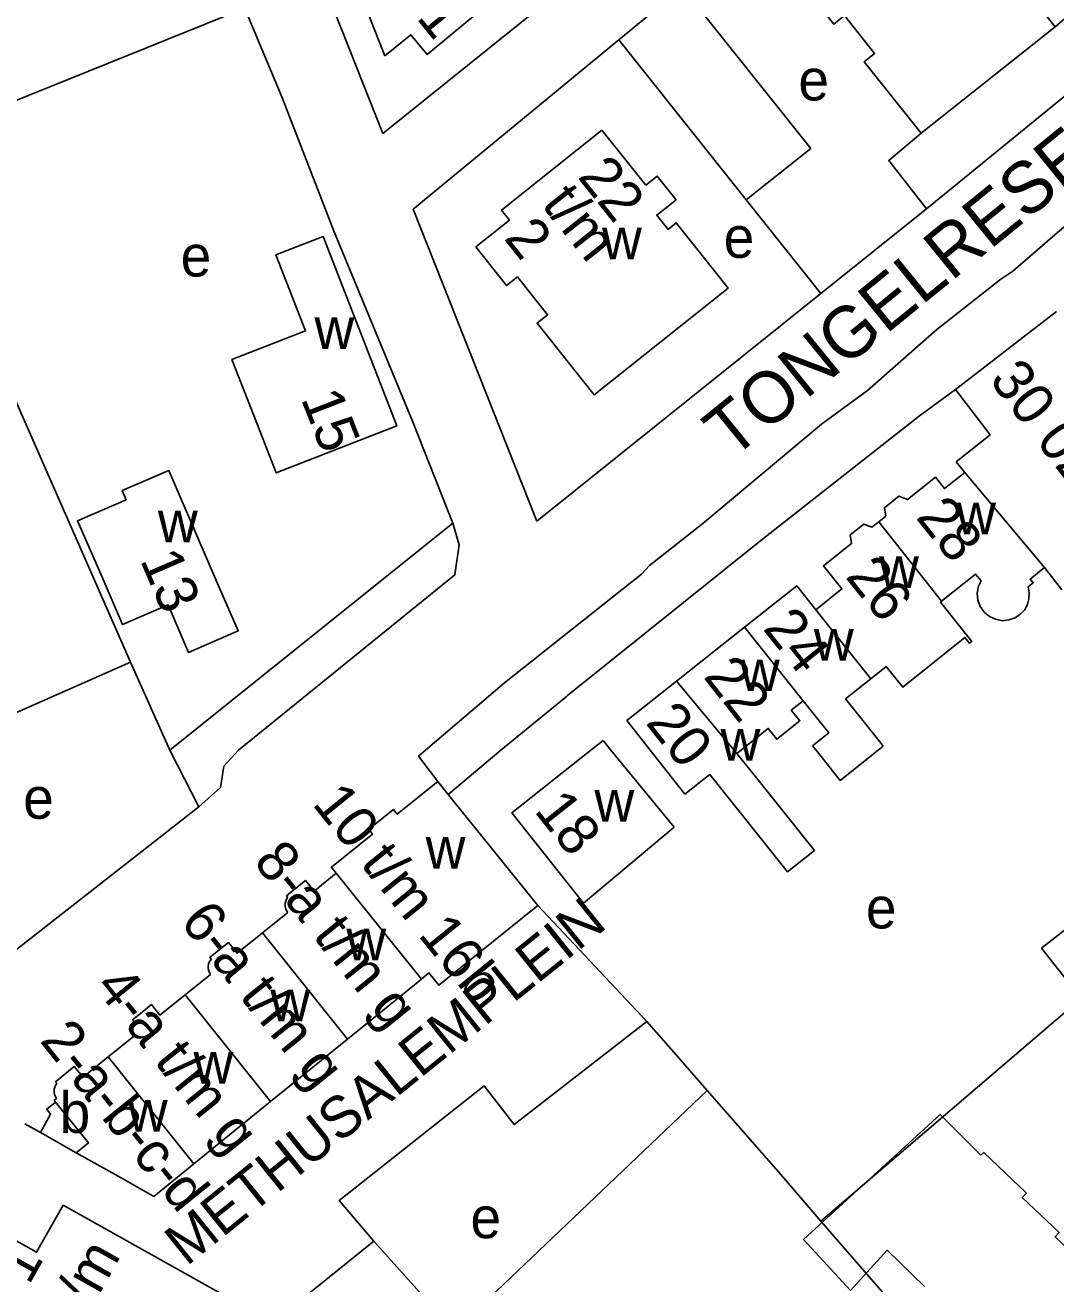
# Model space of a CAD drawing. Extents: x 161141 to 163125, y 381621 to 383200.
# Drawn here: x 161934.5 to 162034.5, y 382848.2 to 382970.4 of the extents above; entities that cross this region are included whole.
import ezdxf

# ---------------------------------------------------------------- set-up
doc = ezdxf.new("R2010")
doc.units = 0
for name, color, linetype in [('BLT_Basislijn', 7, 'Continuous'), ('BLT_Bebouwing', 7, 'Continuous'), ('BLT_Centroide', 7, 'Continuous'), ('BLT_Huisnummer', 7, 'Continuous'), ('BLT_Huisnummer_ tussenligend', 7, 'Continuous'), ('BLT_Huisnummer_reeks', 7, 'Continuous'), ('BLT_Onderverdeling_panden', 7, 'Continuous'), ('BLT_Plantopo', 7, 'Continuous'), ('BLT_Straatnaam', 7, 'Continuous'), ('BLT_Straatnaam_verkleind', 7, 'Continuous')]:
    doc.layers.add(name, color=color, linetype=linetype)

msp = doc.modelspace()

# ---------------------------------------------------------------- linework, layer by layer
at = {"layer": 'BLT_Basislijn'}
for p, q in [((161998.24, 382974.04), (161992.06, 382968.95)), ((162039.04, 382974.17), (162034.4, 382970.22)), ((161932.99, 382962.83), (161955.76, 382972.02)), ((161992.06, 382968.95), (161972.09, 382952.52)), ((161992.06, 382968.95), (162004.41, 382953.43)), ((162004.41, 382953.43), (162011.65, 382944.32)), ((162021.23, 382932.46), (162024.72, 382935.01)), ((162005.82, 382920.35), (162021.23, 382932.46)), ((161975.96, 382922.03), (161948.48, 382899.99)), ((162005.82, 382920.35), (161987.09, 382905.31)), ((161948.48, 382899.99), (161944.66, 382908.56)), ((161951.29, 382894.51), (161948.48, 382899.99)), ((161951.29, 382894.51), (161926.84, 382875.38)), ((161984.18, 382884.91), (161994.76, 382873.68)), ((162036.9, 382875.89), (162011.67, 382854.3)), ((161997.81, 382870.19), (161994.76, 382873.68)), ((162000.63, 382866.97), (161997.81, 382870.19)), ((161934.42, 382863.74), (161935.93, 382862.88)), ((162046.28, 382814.44), (162011.67, 382854.3)), ((161961.29, 382846.71), (161968.27, 382852.33))]:
    msp.add_line(p, q, dxfattribs=at)
for points in [[(161959.96, 382983.09), (161969.17, 382959.86), (162047.68, 383022.98)], [(162055.07, 383020.8), (162073.06, 382998.55), (162074.21, 382996.11), (162061.33, 382985.3), (162036.1, 382964.14), (162021.9, 382952.54)], [(161998.24, 382974.04), (162010.67, 382958.41), (162004.41, 382953.43)], [(161955.76, 382972.02), (161956.08, 382971.21), (161959.35, 382963.42), (161964.45, 382950.31), (161972.02, 382931.93), (161975.96, 382922.03)], [(162051.8, 382964.24), (162051.59, 382964.07), (162034.86, 382950.43), (162030.3, 382946.48), (162029.11, 382945.73), (162022.92, 382940.82), (162016.17, 382934.9), (162011.73, 382931.63), (162000.21, 382922), (161995.04, 382917.92), (161994.27, 382917.07), (161980.96, 382906.53), (161973.3, 382900), (161972.62, 382899.42), (161974.49, 382896.95)], [(162021.4, 382959.88), (162018.24, 382957.25), (162021.9, 382952.54)], [(161984.09, 382922.23), (161972.09, 382952.52)], [(162021.9, 382952.54), (162011.65, 382944.32)], [(162011.65, 382944.32), (161984.09, 382922.23)], [(161975.96, 382922.03), (161976.57, 382919.93), (161976.13, 382917.01), (161955.14, 382900), (161953.74, 382898.46), (161953.42, 382896.39), (161951.29, 382894.51)], [(161987.09, 382905.31), (161986.94, 382905.19), (161980.62, 382900), (161975.5, 382895.7)], [(162036.9, 382875.89), (162033.07, 382880.77), (162048.7, 382892.97)], [(161968.27, 382852.33), (161964.93, 382856.3), (161978.99, 382867.42), (161981.89, 382863.68), (161994.76, 382873.68)], [(162000.63, 382866.97), (161976.12, 382843.61), (161968.27, 382852.33)], [(162011.67, 382854.3), (162007.54, 382859.06), (162000.63, 382866.97)]]:
    msp.add_lwpolyline(points, dxfattribs=at)
at = {"layer": 'BLT_Bebouwing'}
for p, q in [((162024.72, 382935.01), (162034.52, 382942.57)), ((161930.52, 382940.74), (161944.66, 382908.56)), ((162025.62, 382926.97), (162024.8, 382927.98)), ((162033.36, 382917.72), (162035.04, 382915.55)), ((162023.37, 382914.47), (162023.26, 382914.38)), ((161989.35, 382900), (161990.54, 382900.94)), ((161990.54, 382900.94), (161991.29, 382900)), ((162010.86, 382900.41), (162011.19, 382900)), ((162017.71, 382900.38), (162017.23, 382900)), ((161975.5, 382895.7), (161974.49, 382896.95)), ((161957.47, 382882.28), (161959.93, 382884.26)), ((161949.98, 382876.26), (161952.44, 382878.24)), ((161965.72, 382871.96), (161972.9, 382877.79)), ((161942.51, 382870.24), (161944.95, 382872.2)), ((161958.26, 382865.9), (161965.72, 382871.96)), ((161950.82, 382859.85), (161958.26, 382865.9)), ((161939.4, 382860.92), (161935.93, 382862.88))]:
    msp.add_line(p, q, dxfattribs=at)
for points in [[(162021.4, 382959.88), (162015.87, 382966.83), (162016.87, 382967.63), (162013.95, 382971.31), (162012.91, 382970.48), (162009.92, 382974.24), (162013.19, 382976.83), (162012.41, 382977.82), (162022.16, 382985.58), (162026.42, 382980.23), (162027.52, 382981.11), (162029.35, 382978.82), (162027.47, 382977.32), (162028.57, 382975.93), (162029.35, 382976.56), (162034.4, 382970.22)], [(161977.96, 382971.24), (161973.46, 382967.52), (161971.87, 382969.44), (161969.36, 382967.41), (161966.93, 382973.59), (161972.39, 382978.09)], [(162034.4, 382970.22), (162021.4, 382959.88)], [(161958.79, 382948.07), (161963.36, 382949.85), (161970.52, 382931.48), (161958.81, 382926.92), (161956.99, 382931.58), (161954.52, 382937.91), (161961.66, 382940.69), (161958.79, 382948.07)], [(162024.8, 382927.98), (162028.1, 382930.61), (162024.72, 382935.01)], [(161953.13, 382916.17), (161948.38, 382927.14), (161943.88, 382925.2), (161944.26, 382924.31), (161939.54, 382922.27), (161941.92, 382916.78), (161943.91, 382912.19), (161948.32, 382914.1), (161950.31, 382909.49), (161955.12, 382911.59), (161953.13, 382916.17)], [(162025.62, 382926.97), (162023.65, 382925.4), (162022.77, 382926.49), (162020.06, 382924.32), (162019.22, 382924.65), (162017.83, 382923.54), (162017.96, 382922.72), (162017.28, 382922.18)], [(162017.28, 382922.18), (162016.61, 382921.64), (162015.83, 382921.94), (162014.5, 382920.89), (162014.63, 382920.07), (162011.9, 382917.9), (162013.7, 382915.66), (162011.17, 382913.64)], [(162033.36, 382917.72), (162031.98, 382916.61), (162032.27, 382916.25), (162031.77, 382915.85), (162031.88, 382915.28), (162031.84, 382914.7), (162031.71, 382914.18), (162031.44, 382913.63), (162031.01, 382913.2), (162030.51, 382912.86), (162029.91, 382912.64), (162029.27, 382912.57), (162028.59, 382912.71), (162028.03, 382912.99), (162027.54, 382913.38), (162027.11, 382913.94), (162026.9, 382914.55), (162026.84, 382915.24), (162026.96, 382915.91), (162027.21, 382916.43), (162026.67, 382917.1), (162023.37, 382914.47)], [(162011.17, 382913.64), (162009.32, 382915.95), (162004.24, 382911.93)], [(162023.26, 382914.38), (162026.31, 382910.56), (162026.09, 382910.38), (162025.64, 382910.94), (162019.6, 382906.12), (162018.01, 382908.12), (162016.52, 382906.93)], [(161997.65, 382906.71), (162000, 382908.57), (162004.24, 382911.93)], [(161944.66, 382908.56), (161925.31, 382900), (161922.35, 382898.69)], [(161992.82, 382902.88), (161997.65, 382906.71)], [(162016.52, 382906.93), (162014.06, 382904.97), (162017.28, 382900.93), (162017.71, 382900.38)], [(162009.94, 382904.8), (162008.79, 382903.88), (162009.62, 382902.85), (162007.38, 382901.07), (162006.55, 382902.11), (162003.52, 382899.69)], [(162010.86, 382900.41), (162012.43, 382901.67), (162009.94, 382904.8)], [(162003.52, 382899.69), (162005.55, 382897.14), (162011.04, 382890.27), (162008.43, 382888.19), (162000.89, 382897.64), (162000, 382896.95), (161998.47, 382895.74), (161995.1, 382900), (161992.82, 382902.88)], [(161989.35, 382900), (161981.68, 382893.93), (161988.63, 382885.16), (161997.42, 382892.53), (161991.29, 382900)], [(162017.23, 382900), (162013.54, 382897.05), (162011.19, 382900)], [(161964.64, 382888.06), (161964.17, 382888.65), (161968.15, 382891.86), (161967.8, 382892.34), (161970.18, 382894.25), (161970.56, 382893.78), (161974.49, 382896.95)], [(161984.18, 382884.91), (161975.5, 382895.7)], [(161960.72, 382886.61), (161961.64, 382887.36), (161962.48, 382886.32), (161964.64, 382888.06)], [(161959.92, 382885.72), (161959.8, 382885.85), (161960.72, 382886.61)], [(161959.92, 382885.72), (161959.77, 382885.45), (161959.68, 382885.16), (161959.68, 382884.85), (161959.75, 382884.56), (161959.9, 382884.29), (161959.93, 382884.26)], [(161972.9, 382877.79), (161973.63, 382878.38), (161974.59, 382877.19), (161984.18, 382884.91)], [(161953.28, 382880.61), (161954.18, 382881.33), (161955.01, 382880.3), (161957.47, 382882.28)], [(161952.36, 382879.54), (161952.54, 382879.69), (161952.38, 382879.88), (161953.28, 382880.61)], [(161952.36, 382879.54), (161952.25, 382879.25), (161952.21, 382878.94), (161952.25, 382878.64), (161952.37, 382878.35), (161952.44, 382878.24)], [(161945.79, 382874.58), (161946.7, 382875.32), (161947.52, 382874.27), (161949.98, 382876.26)], [(161945, 382873.69), (161944.88, 382873.84), (161945.79, 382874.58)], [(161945, 382873.69), (161944.83, 382873.42), (161944.74, 382873.12), (161944.73, 382872.81), (161944.8, 382872.5), (161944.94, 382872.22), (161944.95, 382872.2)], [(161937.53, 382867.67), (161937.4, 382867.8), (161939.21, 382869.3), (161940.08, 382868.27), (161942.51, 382870.24)], [(161937.53, 382867.67), (161937.37, 382867.4), (161937.28, 382867.1), (161937.27, 382866.78), (161937.34, 382866.47), (161937.48, 382866.19), (161937.49, 382866.18)], [(161935.93, 382862.88), (161936.92, 382864.67), (161936.54, 382865.17), (161937.39, 382865.84)], [(161937.39, 382865.84), (161937.27, 382866.01), (161937.49, 382866.18)], [(161950.82, 382859.85), (161946.94, 382856.69), (161943.76, 382858.48), (161939.4, 382860.92)], [(161921.65, 382853.48), (161925.76, 382856.78), (161935.56, 382851.27), (161938.14, 382855.85)], [(161938.14, 382855.85), (161955.63, 382846.03)]]:
    msp.add_lwpolyline(points, dxfattribs=at)
msp.add_lwpolyline([(161990.42, 382960.19), (161994.68, 382954.85), (161995.78, 382955.73), (161997.61, 382953.43), (161995.73, 382951.94), (161996.83, 382950.55), (161997.62, 382951.18), (162002.66, 382944.84), (161989.66, 382934.5), (161984.13, 382941.45), (161985.13, 382942.25), (161982.21, 382945.93), (161981.17, 382945.1), (161978.18, 382948.85), (161981.45, 382951.45), (161980.67, 382952.43)], close=True, dxfattribs=at)
at = {"layer": 'BLT_Onderverdeling_panden'}
for p, q in [((162033.36, 382917.72), (162025.62, 382926.97)), ((162017.28, 382922.18), (162023.37, 382914.47)), ((162011.17, 382913.64), (162016.52, 382906.93)), ((162004.24, 382911.93), (162009.94, 382904.8)), ((161997.65, 382906.71), (162003.52, 382899.69)), ((161964.64, 382888.06), (161972.9, 382877.79)), ((161957.47, 382882.28), (161965.72, 382871.96)), ((161949.98, 382876.26), (161958.26, 382865.9)), ((161942.51, 382870.24), (161950.82, 382859.85))]:
    msp.add_line(p, q, dxfattribs=at)
msp.add_lwpolyline([(161939.4, 382860.92), (161940.59, 382861.88), (161937.39, 382865.84)], dxfattribs=at)
at = {"layer": 'BLT_Plantopo'}
msp.add_lwpolyline([(162021.72, 382847.94), (162018.1, 382851.46), (162014.52, 382847.57), (162009.98, 382852.51), (162023.22, 382864.65), (162027.18, 382860.7), (162027.47, 382860.94), (162031.61, 382857.01), (162031.2, 382856.58), (162034.77, 382853.19), (162034.39, 382852.78), (162038.08, 382849.28), (162037.69, 382848.87), (162041.31, 382845.43)], dxfattribs=at)

# ---------------------------------------------------------------- texts
at = {"layer": 'BLT_Centroide'}
for s, p in [('e', (162009.48, 382963.07)), ('w', (161990.42, 382947.64)), ('e', (162002.23, 382947.79)), ('e', (161949.54, 382945.98)), ('w', (161962.52, 382938.95)), ('w', (161947.33, 382920.17)), ('w', (162024.78, 382920.94)), ('w', (162017.3, 382915.73)), ('w', (162010.98, 382908.69)), ('w', (162003.8, 382905.73)), ('w', (162001.92, 382898.97)), ('e', (161934.26, 382893.35)), ('w', (161989.69, 382893.06)), ('w', (161973.31, 382888.5)), ('e', (162016.03, 382882.7)), ('w', (161965.62, 382879.61)), ('w', (161958.25, 382873.67)), ('w', (161950.78, 382867.64)), ('b', (161937.79, 382862.85)), ('w', (161944.41, 382862.98)), ('e', (161977.66, 382852.64))]:
    msp.add_text(s, height=4, dxfattribs=at).set_placement(p)
at = {"layer": 'BLT_Huisnummer'}
for s, rotation, p in [('1', 309.2052, (161972.34, 382971.07)), ('15', 291.2843, (161961.18, 382934.14)), ('13', 293.4122, (161945.56, 382918.47)), ('26', 308.5922, (162013.96, 382916.83)), ('24', 308.5922, (162005.95, 382911.79)), ('20', 308.3616, (161994.58, 382902.65)), ('18', 308.3777, (161983.76, 382894.12))]:
    msp.add_text(s, height=4, rotation=rotation, dxfattribs=at).set_placement(p)
at = {"layer": 'BLT_Huisnummer_ tussenligend'}
for s, rotation, p in [('28', 308.5942, (162020.79, 382922.59)), ('22', 308.3616, (162000.18, 382907.12))]:
    msp.add_text(s, height=4, rotation=rotation, dxfattribs=at).set_placement(p)
at = {"layer": 'BLT_Huisnummer_reeks'}
for s, rotation, p in [('22', 308.5068, (161987.98, 382955.64)), ('t/m', 308.5074, (161984.48, 382952.94)), ('2', 308.5067, (161980.83, 382949.68)), ('30 02 t/m 30 40', 307.5492, (162027.91, 382935.93)), ('10 t/m 16b', 308.9445, (161962.22, 382894.77)), ('8-a t/m g', 308.8461, (161956.5, 382889.15)), ('6-a t/m g', 308.8461, (161949.39, 382883.3)), ('4-a t/m g', 308.8461, (161941.1, 382876.99)), ('2-a-b-c-d', 308.903, (161935.79, 382871.78)), ('1', 60.6613, (161934.82, 382848.01)), ('t/m', 60.6939, (161940.16, 382844.48))]:
    msp.add_text(s, height=4, rotation=rotation, dxfattribs=at).set_placement(p)
at = {"layer": 'BLT_Straatnaam'}
msp.add_text('TONGELRESESTRAAT', height=5, rotation=39.114, dxfattribs=at).set_placement((162002.98, 382928.13))
at = {"layer": 'BLT_Straatnaam_verkleind'}
msp.add_text('METHUSALEMPLEIN', height=4, rotation=38.8657, dxfattribs=at).set_placement((161950.11, 382849.85))

doc.saveas('drawing.dxf')
